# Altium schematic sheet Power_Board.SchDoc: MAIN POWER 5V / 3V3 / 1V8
size A4; Date: Not used; ApprovedBy: Not used; CheckedBy: Not used; Author: Not used; CompanyName: STMicroelectronics; DrawnBy: Not used; Engineer: Not used; Organization: Not used; Address1: Not used; Address2: Not used; Address3: Not used; Address4: Not used; DocumentNumber: 9; Revision: Not used; SheetNumber: 8; SheetTotal: 9
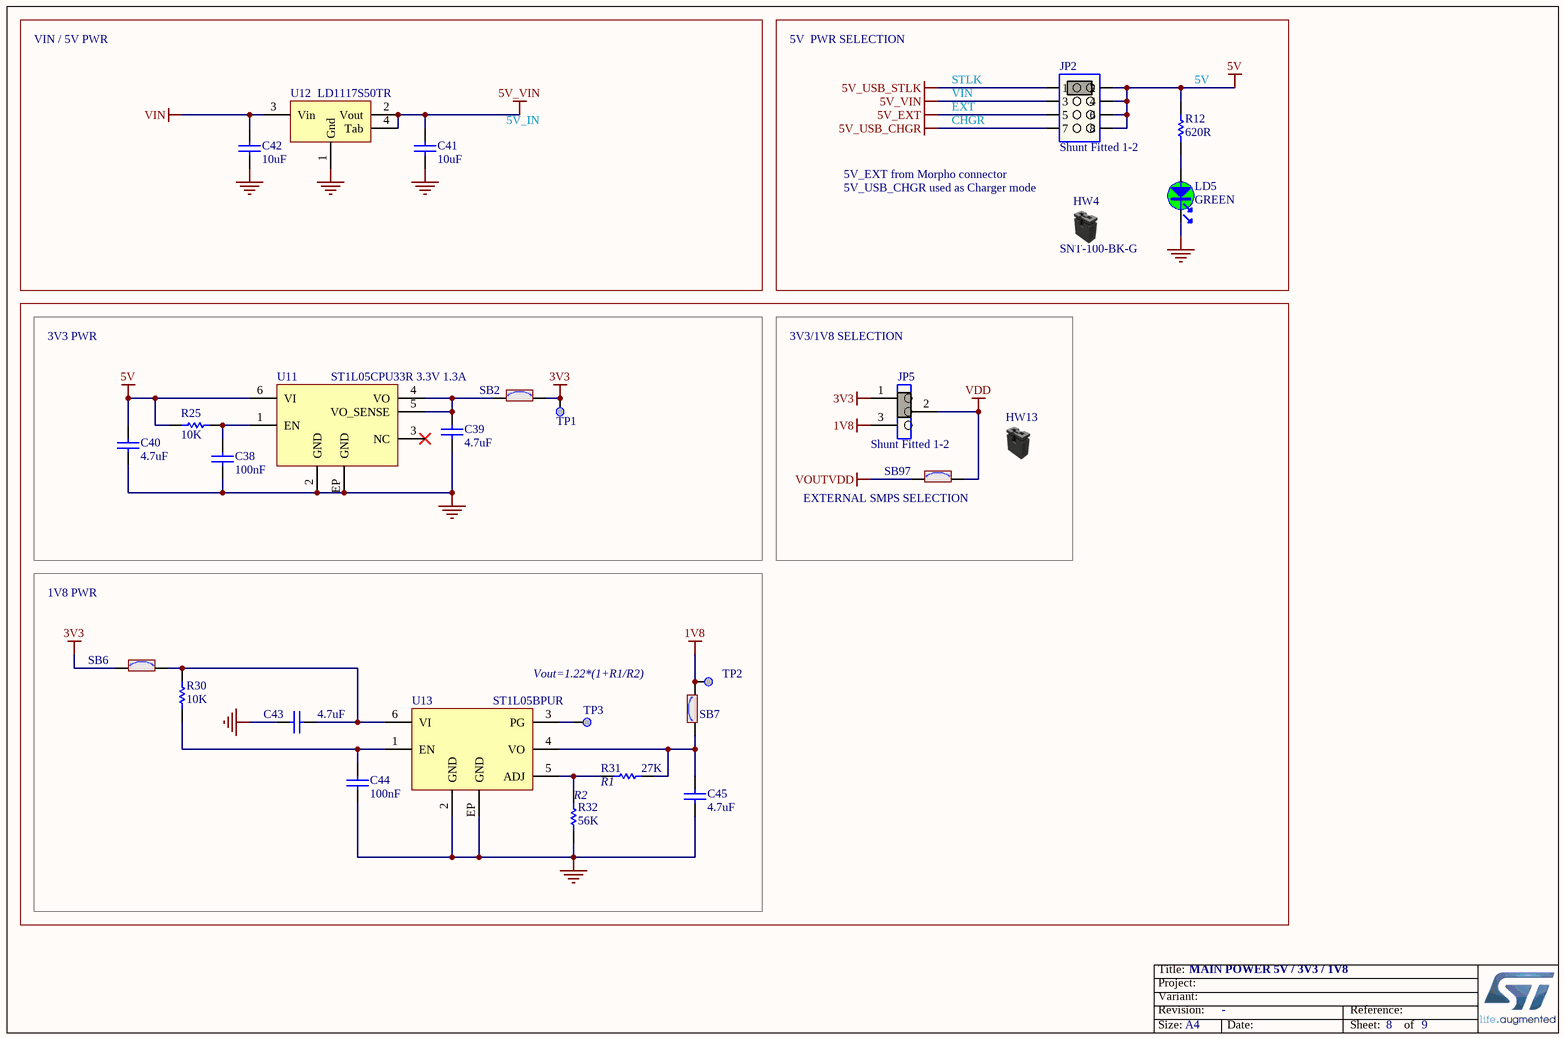
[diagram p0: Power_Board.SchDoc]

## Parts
C38  value 100nF  [C0402]  (hidden comment: Capacitor)
C39  value 4.7uF  [C0603]  (hidden comment: Capacitor)
C40  value 4.7uF  [C0603]  (hidden comment: Capacitor)
C41  value 10uF  [C0805]  (hidden comment: Capacitor)
C42  value 10uF  [C0805]  (hidden comment: Capacitor)
C43  value 4.7uF  [C0603]  (hidden comment: Capacitor)
C44  value 100nF  [C0402]  (hidden comment: Capacitor)
C45  value 4.7uF  [C0603]  (hidden comment: Capacitor)
HW4  value SNT-100-BK-G  (hidden comment: Shunt Black 2.54mm)  (mechanical)
HW13  Shunt Black 2.54mm  (value not drawn)  (mechanical)
JP2  value Shunt Fitted 1-2  [CON_SAMTEC_TSW-104-07-X-D]  (hidden comment: Jumper_Header 4x2 Fitted 1-2)
JP5  value Shunt Fitted 1-2  [CON_SAMTEC_TSW-103-07-F-S]  (hidden comment: Jumper_Header 3x1 Fitted 1-2)
LD5  value GREEN  [LED_0603_OSRAM_LG-Q396-PS-35_GREEN_1A2K_H0P4]  (hidden comment: LED_green)
R12  value 620R  [R0603]  (hidden comment: Resistor)
R25  value 10K  [R0402]  (hidden comment: Resistor)
R30  value 10K  [R0402]  (hidden comment: Resistor)
R31  value 27K  [R0402]  (hidden comment: Resistor)
R32  value 56K  [R0402]  (hidden comment: Resistor)
SB2  SB_ON  [SOLDER-BRIDGE_R0603-0R]  (value not drawn)
SB6  SB_ON  [SOLDER-BRIDGE_R0603-0R]  (value not drawn)
SB7  SB_ON  [SOLDER-BRIDGE_R0603-0R]  (value not drawn)
SB97  SB_ON  [SOLDER-BRIDGE_R0603-0R]  (value not drawn)
TP1  Test Point  [TP_SMD_1MM]  (value not drawn)  (no BOM)
TP2  Test Point  [TP_SMD_1MM]  (value not drawn)  (no BOM)
TP3  Test Point  [TP_SMD_1MM]  (value not drawn)  (no BOM)
U11  value ST1L05CPU33R 3.3V 1.3A  [ICC_DFN6-EPAD_3X3_P095]  (hidden comment: ST1L05CPU33R)
U12  LD1117S50TR  [REG_SOT223-TAB]
U13  ST1L05BPUR  [ICC_DFN6-EPAD_3X3_P095]

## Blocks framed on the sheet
3V3 PWR: C38-C40 R25 SB2 TP1 U11

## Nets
1V8: JP5.3 SB7.2 TP2.1
3V3: JP5.1 SB2.2 SB6.1 TP1.1
5V: C40.2 JP2.2 JP2.4 JP2.6 JP2.8 R12.2 R25.2 U11.6(VI)
5V_EXT: JP2.5
5V_USB_CHGR: JP2.7
5V_USB_STLK: JP2.1
5V_VIN: C41.2 JP2.3 U12.2(Vout) U12.4(Tab)
GND: C38.2 C39.1 C40.1 C41.1 C42.1 C43.2 C44.2 C45.1 LD5.2 R32.1 U11.2(GND) U11.EP(GND) U12.1(Gnd) U13.2(GND) U13.EP(GND)
VDD: JP5.2 SB97.2
VIN: C42.2 U12.3(Vin)
VOUTVDD: SB97.1
NetC38_1: C38.1 R25.1 U11.1(EN)
NetC39_2: C39.2 SB2.1 U11.4(VO) U11.5(VO_SENSE)
NetC43_1: C43.1 R30.1 SB6.2 U13.6(VI)
NetC44_1: C44.1 R30.2 U13.1(EN)
NetC45_2: C45.2 R31.1 SB7.1 U13.4(VO)
NetLD5_1: LD5.1 R12.1
NetR31_2: R31.2 R32.2 U13.5(ADJ)
NetTP3_1: TP3.1 U13.3(PG)

Not connected (* = marked no-connect by the designer): U11 3(NC)*

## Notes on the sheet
- VIN / 5V PWR
- 5V  PWR SELECTION
- STLK
- VIN
- EXT
- (near R12) 5V
- 5V_IN
- 5V_EXT from Morpho connector
- CHGR
- 5V_USB_CHGR used as Charger mode
- 3V3/1V8 SELECTION
- (near SB97) EXTERNAL SMPS SELECTION
- 1V8 PWR
- Vout=1.22*(1+R1/R2)
- (near R31) R1
- (near R32) R2

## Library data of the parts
C38 C44 = MCD-00006: Capacitor, MLCC, 100nF, 16V, X7R, 10%, 0402, T=0.5mm; Manufacturer_Part_Number: CC0402KRX7R7BB104; Manufacturer: YAGEO; Alternate_Manufacturer_Part_Number: GCM155R71C104KA55D; Alternate_Manufacturer: MURATA; Provided_By: SUBCO; ECCN_US: EAR99; ECCN_EU: NEC
C39 C43 C45 = MCD-01121: Capacitor, MLCC, 4.7µF, 10V, X5R, 20%, 0603, T=0,8mm; Manufacturer_Part_Number: GRM188R61A475ME15; Manufacturer: MURATA; Provided_By: SUBCO; ECCN_US: EAR99; ECCN_EU: NEC
C40 = MCD-00097: Capacitor, MLCC, 4.7uF, 16V, X5R, 20%, 0603, T=0,8mm; Manufacturer_Part_Number: GRM188R61C475KE11; Manufacturer: MURATA; Alternate_Manufacturer_Part_Number: GRM188R61C475MAAJ; Provided_By: SUBCO; ECCN_US: EAR99; ECCN_EU: NEC
C41 C42 = MCD-00014: Capacitor, MLCC, 10uF, 25V, X5R, 10%, 0805, T=0,85mm; Manufacturer_Part_Number: CC0805KRX5R8BB106; Manufacturer: YAGEO; Provided_By: SUBCO; ECCN_US: EAR99; ECCN_EU: NEC
HW4 = MCD-00043: SHUNT 2.54mm BLACK; Manufacturer: SAMTEC; Part_Type: Mechanical; Alternate_Manufacturer_Part_Number: 316102S111A; Alternate_Manufacturer: JIUBABA; Provided_By: SUBCO
HW13 = MCD-00043: SHUNT 2.54mm BLACK; Manufacturer_Part_Number: SNT-100-BK-G; Manufacturer: SAMTEC; Part_Type: Mechanical; Alternate_Manufacturer_Part_Number: 316102S111A; Alternate_Manufacturer: JIUBABA; Provided_By: SUBCO
JP2 = MCD-00686: Header, 4x2, 2,54mm, VR, TH, Height 5.84mm/2.54mm - Shunt Fitted 1-2; Part_Type: Connector; Manufacturer_Part_Number: TSW-104-07-x-D; Manufacturer: SAMTEC; Provided_By: SUBCO
JP5 = MCD-00684: Header, 3x1, 2,54mm, VR, TH, Height 5.84mm/2.54mm - Shunt Fitted 1-2 by default; Part_Type: Connector; Manufacturer_Part_Number: TSW-103-07-F-S; Manufacturer: SAMTEC; Provided_By: SUBCO
LD5 = MCD-00588: LED Green, 0603 SMD, Forward Voltage Typ=2V, Max=2.5V; Part_Type: Display; Manufacturer_Part_Number: LG Q396-PS-35; Manufacturer: OSRAM OPTO SEMICONDUCTORS; Alternate_Manufacturer_Part_Number: VLMTG1300-GS08; Alternate_Manufacturer: VISHAY SEMICONDUCTOR OPTO DIVISION; Provided_By: SUBCO
R12 = MCD-00500: Resistor,620R,0603,1%,1/10W; Manufacturer_Part_Number: RC0603FR-07620RL; Manufacturer: YAGEO; Provided_By: SUBCO; ECCN_US: EAR99; ECCN_EU: NEC
R25 R30 = MCD-00053: Resistor,10K,0402,1%,1/16W; Manufacturer_Part_Number: RC0402FR-0710KL; Manufacturer: YAGEO; Provided_By: SUBCO; ECCN_US: EAR99; ECCN_EU: NEC
R31 = MCD-00443: Resistor,27K,0402,1%,1/16W; Manufacturer_Part_Number: RC0402FR-0727KL; Manufacturer: YAGEO; Provided_By: SUBCO; ECCN_US: EAR99; ECCN_EU: NEC
R32 = MCD-00493: Resistor,56K,0402,1%,1/16W; Manufacturer_Part_Number: RC0402FR-0756KL; Manufacturer: YAGEO; Provided_By: SUBCO; ECCN_US: EAR99; ECCN_EU: NEC
SB2 SB6 SB7 SB97 = MCD-00071: Solder Bridge ON; Part_Type: Mechanical; Manufacturer_Part_Number: RC0603JR-070RL; Manufacturer: YAGEO; Provided_By: SUBCO
TP1-TP3 = MCD-00074: Test Point 1mm; Part_Type: Mechanical
U11 = MCD-01025: LDO, 3.3V, 1.3A, Very low quiescent current BiCMOS voltage regulator; Part_Type: IC; Manufacturer: STMICROELECTRONICS; BMS_Part_Number: 9176246; Provided_By: SUBCO with ST control; ECCN_US: EAR99; ECCN_EU: NEC
U12 = MCD-00088: IC REG LDO 5V 0.8A SOT223; Manufacturer: STMICROELECTRONICS; BMS_Part_Number: 9176133; Provided_By: SUBCO with ST control; ECCN_US: EAR99; ECCN_EU: NEC
U13 = MCD-00581: LDO Linear Voltage Regulator IC Positive Adjustable 1 Output Adjustable 1.3A 6-DFN (3x3); Manufacturer: STMICROELECTRONICS; BMS_Part_Number: 9176239; Provided_By: SUBCO with ST control; ECCN_US: EAR99; ECCN_EU: NEC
